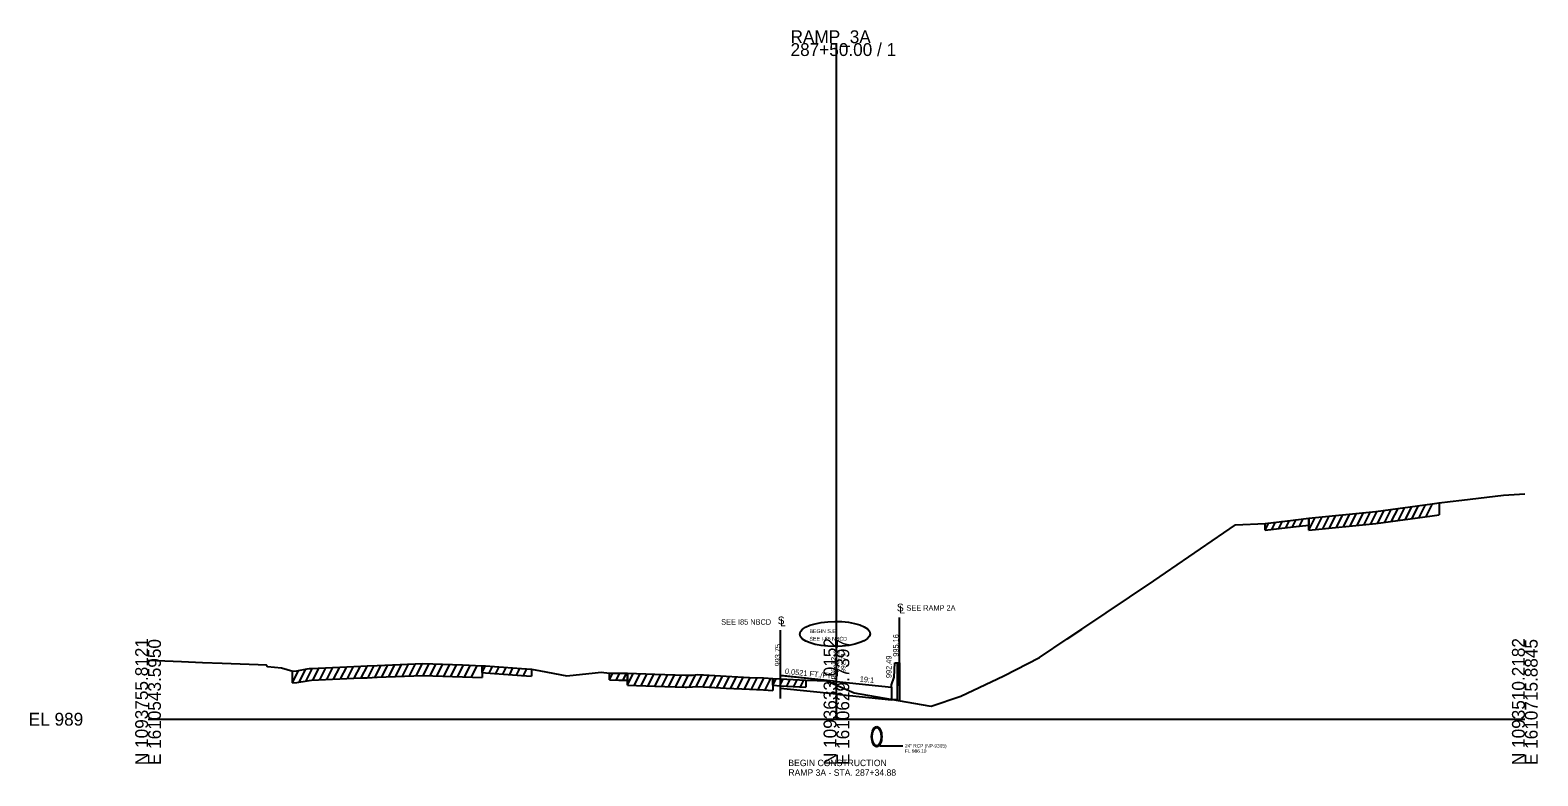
# Model space of a CAD drawing. Extents: x -26 to 1611524, y -12 to 1281970.
# Drawn here: x -25.7 to 302.8, y -12.4 to 150.3 of the extents above; entities that cross this region are included whole.
import ezdxf

# ---------------------------------------------------------------- set-up
doc = ezdxf.new("R2010")
doc.units = 0
for name, color, linetype in [('RD_EX_Misc', 7, 'Continuous'), ('RD_GPK_XS_Cell', 7, 'Continuous'), ('RD_Sketch1', 7, 'Continuous'), ('RD_Sketch6', 7, 'Continuous'), ('RD_XS_Base', 7, 'Continuous'), ('RD_XS_CurbFront', 7, 'Continuous'), ('RD_XS_ExGround', 7, 'Continuous'), ('RD_XS_ExPaveRet', 7, 'Continuous'), ('RD_XS_MatchLine', 7, 'Continuous'), ('RD_XS_MedBbase', 7, 'Continuous'), ('RD_XS_MedBWall', 7, 'Continuous'), ('RD_XS_Pave', 7, 'Continuous'), ('RD_XS_PaveShd', 7, 'Continuous'), ('RD_XS_Pipe', 7, 'Continuous'), ('RD_XS_TX_Elev_EX', 7, 'Continuous'), ('RD_XS_TX_Elev_PR', 7, 'Continuous'), ('RD_XS_TX_MatchLine', 7, 'Continuous'), ('RD_XS_TX_Notes', 7, 'Continuous'), ('RD_XS_TX_ShdSlope', 7, 'Continuous'), ('RD_XS_TX_Slope', 7, 'Continuous')]:
    doc.layers.add(name, color=color, linetype=linetype)

msp = doc.modelspace()

# ---------------------------------------------------------------- linework, layer by layer
at = {"layer": 'RD_EX_Misc'}
for p, q in [((252.97, 43.85), (252.97, 42.35)), ((243.4, 41.2), (243.4, 42.7)), ((243.4, 41.2), (249.5, 41.93)), ((249.5, 41.93), (252.96, 42.35)), ((252.96, 42.35), (252.97, 42.35)), ((72.8, 10.17), (72.8, 11.67)), ((72.8, 10.17), (73.52, 10.12)), ((73.52, 10.12), (81.35, 9.57)), ((83.54, 10.89), (83.54, 9.39)), ((100.53, 8.57), (100.53, 10.07)), ((104.46, 10.03), (104.46, 8.53)), ((81.35, 9.57), (83.54, 9.39)), ((100.53, 8.57), (102.6, 8.54)), ((102.6, 8.54), (104.46, 8.53)), ((136.17, 7.39), (136.17, 8.89)), ((136.17, 7.39), (137.8, 7.29)), ((137.8, 7.29), (143.32, 7.01)), ((143.32, 8.51), (143.32, 7.01))]:
    msp.add_line(p, q, dxfattribs=at)
at = {"layer": 'RD_GPK_XS_Cell'}
for p, q in [((150, 0), (150, 147.42)), ((0, 0), (150, 0)), ((150, 0), (300, 0))]:
    msp.add_line(p, q, dxfattribs=at)
at = {"layer": 'RD_Sketch1'}
for p, q in [((243.4, 41.2), (244.2, 42.8)), ((244.9, 41.38), (245.7, 42.98)), ((246.4, 41.56), (247.2, 43.16)), ((247.91, 41.74), (248.7, 43.34)), ((249.41, 41.92), (250.2, 43.52)), ((250.91, 42.1), (251.7, 43.7)), ((72.8, 10.17), (73.53, 11.62)), ((74.3, 10.07), (75.02, 11.52)), ((75.8, 9.96), (76.52, 11.41)), ((77.3, 9.86), (78.02, 11.3)), ((78.8, 9.75), (79.52, 11.2)), ((80.3, 9.64), (81.02, 11.09)), ((81.8, 9.53), (82.52, 10.97)), ((100.53, 8.57), (101.27, 10.06)), ((102.03, 8.55), (102.77, 10.04)), ((103.53, 8.54), (104.28, 10.03)), ((136.17, 7.39), (136.9, 8.84)), ((137.68, 7.3), (138.41, 8.76)), ((139.18, 7.22), (139.91, 8.69)), ((140.68, 7.15), (141.41, 8.61)), ((142.18, 7.07), (142.91, 8.53))]:
    msp.add_line(p, q, dxfattribs=at)
at = {"layer": 'RD_Sketch6'}
msp.add_line((150, 8.23), (138, 9.48), dxfattribs=at)
at = {"layer": 'RD_XS_Base'}
for p, q in [((137.79, 6.72), (137.79, 8.79)), ((150, 5.45), (137.79, 6.72)), ((150, 5.45), (162, 4.2))]:
    msp.add_line(p, q, dxfattribs=at)
at = {"layer": 'RD_XS_CurbFront'}
for p, q in [((163.25, 12.31), (163.25, 11.65)), ((162, 6.98), (162, 4.2))]:
    msp.add_line(p, q, dxfattribs=at)
at = {"layer": 'RD_XS_ExGround'}
msp.add_lwpolyline([(0, 12.87), (7.28, 12.59), (11.83, 12.4), (16.15, 12.23), (23.97, 11.94), (25.76, 11.84), (25.99, 11.51), (29.09, 11.21), (31.52, 10.5), (32.43, 10.58), (34.64, 11), (35.13, 11.05), (35.59, 11.09), (46.39, 11.6), (47.74, 11.66), (49.94, 11.75), (59.88, 12.15), (68.49, 11.83), (72.8, 11.67), (73.52, 11.62), (81.35, 11.07), (83.54, 10.89), (85.55, 10.55), (91.26, 9.48), (97.46, 10.13), (98.71, 10.23), (100.53, 10.07), (102.6, 10.04), (104.46, 10.03), (110.42, 9.82), (117.03, 9.61), (117.37, 9.61), (118.65, 9.63), (119.81, 9.73), (126, 9.4), (131.09, 9.13), (134.08, 9), (136.17, 8.89), (137.8, 8.79), (143.32, 8.51), (145.79, 8.44), (147.77, 8.43), (150, 7.43), (153.86, 5.74), (170.15, 2.93), (170.63, 2.84), (177.13, 5.05), (186.51, 9.46), (194.23, 13.47), (200.29, 17.56), (203.5, 19.61), (219.16, 30.18), (236.93, 42.4), (243.4, 42.7), (249.5, 43.43), (252.96, 43.85), (267.54, 45.31), (279.79, 46.97), (281.32, 47.19), (283.71, 47.46), (286.29, 47.77), (295.34, 48.86), (300, 49.13)], dxfattribs=at)
at = {"layer": 'RD_XS_ExPaveRet'}
for p, q in [((272.47, 43.38), (273.87, 46.17)), ((273.97, 43.58), (275.37, 46.37)), ((275.47, 43.79), (276.87, 46.58)), ((276.97, 43.99), (278.37, 46.78)), ((278.47, 44.2), (279.87, 46.99)), ((281.32, 47.19), (281.32, 44.59)), ((252.97, 41.25), (254.33, 43.99)), ((252.97, 41.25), (252.97, 43.85)), ((254.47, 41.4), (255.83, 44.14)), ((255.97, 41.55), (257.34, 44.29)), ((257.47, 41.7), (258.84, 44.44)), ((258.97, 41.85), (260.34, 44.59)), ((260.47, 42), (261.84, 44.74)), ((261.97, 42.15), (263.34, 44.89)), ((263.47, 42.3), (264.84, 45.04)), ((264.97, 42.45), (266.34, 45.19)), ((266.47, 42.6), (267.84, 45.35)), ((267.54, 42.71), (279.79, 44.37)), ((267.97, 42.77), (269.37, 45.56)), ((269.47, 42.97), (270.87, 45.76)), ((270.97, 43.18), (272.37, 45.97)), ((279.79, 44.37), (281.32, 44.59)), ((281.32, 44.59), (281.32, 44.59)), ((252.97, 41.25), (267.54, 42.71)), ((31.44, 7.92), (32.81, 10.65)), ((31.44, 7.92), (31.44, 10.52)), ((32.94, 8.08), (34.38, 10.95)), ((34.44, 8.36), (35.81, 11.1)), ((35.94, 8.51), (37.27, 11.17)), ((37.44, 8.58), (38.77, 11.24)), ((38.94, 8.65), (40.27, 11.31)), ((40.44, 8.72), (41.78, 11.38)), ((41.94, 8.79), (43.28, 11.45)), ((43.44, 8.86), (44.78, 11.52)), ((44.94, 8.93), (46.28, 11.59)), ((46.45, 9), (47.78, 11.67)), ((47.95, 9.07), (49.27, 11.73)), ((49.45, 9.13), (50.77, 11.79)), ((50.95, 9.19), (52.27, 11.85)), ((52.45, 9.25), (53.77, 11.91)), ((53.95, 9.31), (55.27, 11.97)), ((55.45, 9.37), (56.78, 12.03)), ((56.95, 9.43), (58.28, 12.09)), ((58.45, 9.49), (59.78, 12.15)), ((59.95, 9.55), (61.23, 12.1)), ((61.45, 9.49), (62.73, 12.04)), ((62.95, 9.44), (64.23, 11.99)), ((64.45, 9.38), (65.73, 11.93)), ((65.95, 9.32), (67.23, 11.87)), ((67.45, 9.27), (68.73, 11.82)), ((68.95, 9.21), (70.23, 11.76)), ((70.45, 9.15), (71.73, 11.71)), ((72.8, 11.67), (72.8, 9.07)), ((104.46, 7.43), (104.46, 10.03)), ((104.46, 7.43), (105.73, 9.99)), ((105.96, 7.38), (107.24, 9.93)), ((107.46, 7.33), (108.74, 9.88)), ((31.44, 7.92), (31.52, 7.9)), ((31.52, 7.9), (32.43, 7.98)), ((32.43, 7.98), (34.64, 8.4)), ((34.64, 8.4), (35.13, 8.45)), ((35.13, 8.45), (35.59, 8.49)), ((35.59, 8.49), (46.39, 9)), ((46.39, 9), (47.74, 9.06)), ((47.74, 9.06), (49.94, 9.15)), ((49.94, 9.15), (59.88, 9.55)), ((59.88, 9.55), (68.49, 9.23)), ((68.49, 9.23), (72.8, 9.07)), ((104.46, 7.43), (110.42, 7.22)), ((108.96, 7.27), (110.24, 9.83)), ((110.42, 7.22), (117.03, 7.01)), ((110.46, 7.22), (111.74, 9.78)), ((111.96, 7.17), (113.24, 9.73)), ((113.46, 7.12), (114.74, 9.68)), ((114.96, 7.08), (116.24, 9.64)), ((116.46, 7.03), (117.76, 9.62)), ((117.03, 7.01), (117.37, 7.01)), ((117.37, 7.01), (118.65, 7.03)), ((117.96, 7.02), (119.29, 9.69)), ((118.65, 7.03), (119.81, 7.13)), ((119.46, 7.1), (120.75, 9.68)), ((119.81, 7.13), (126, 6.8)), ((120.96, 7.07), (122.23, 9.6)), ((122.46, 6.99), (123.73, 9.52)), ((123.96, 6.91), (125.23, 9.44)), ((125.46, 6.83), (126.73, 9.36)), ((126, 6.8), (131.09, 6.53)), ((126.96, 6.75), (128.23, 9.28)), ((128.46, 6.67), (129.73, 9.21)), ((129.97, 6.59), (131.23, 9.13)), ((131.47, 6.52), (132.74, 9.06)), ((132.97, 6.45), (134.24, 8.99)), ((134.47, 6.38), (135.73, 8.91)), ((136.17, 8.89), (136.17, 6.29)), ((131.09, 6.53), (134.08, 6.4)), ((134.08, 6.4), (136.17, 6.29)), ((136.17, 6.29), (136.17, 6.29))]:
    msp.add_line(p, q, dxfattribs=at)
at = {"layer": 'RD_XS_MatchLine'}
for p, q in [((163.75, 12.31), (163.75, 4.03)), ((137.79, 8.79), (137.79, 9.5))]:
    msp.add_line(p, q, dxfattribs=at)
at = {"layer": 'RD_XS_MedBbase'}
for p, q in [((163.75, 11.65), (163.25, 11.65)), ((163.25, 11.65), (163.25, 4.2)), ((163.75, 12.31), (163.75, 11.65)), ((163.25, 4.2), (162, 4.2))]:
    msp.add_line(p, q, dxfattribs=at)
at = {"layer": 'RD_XS_MedBWall'}
for p, q in [((162.58, 9.15), (162.75, 12.31)), ((162.75, 12.31), (163.25, 12.31)), ((163.25, 12.31), (163.75, 12.31)), ((162, 7.48), (162.58, 9.15)), ((162, 6.98), (162, 7.48))]:
    msp.add_line(p, q, dxfattribs=at)
at = {"layer": 'RD_XS_Pave'}
msp.add_line((150, 8.23), (137.79, 9.5), dxfattribs=at)
at = {"layer": 'RD_XS_PaveShd'}
msp.add_line((150, 8.23), (162, 6.98), dxfattribs=at)
at = {"layer": 'RD_XS_Pipe'}
msp.add_line((159.44, -5.81), (164.44, -5.81), dxfattribs=at)
for major_axis in [(0, 2.2), (0, 2)]:
    msp.add_ellipse((158.77, -3.81), major_axis=major_axis, ratio=0.5, dxfattribs=at)
at = {"layer": 'RD_XS_TX_MatchLine'}
for p, q in [((163.75, 12.31), (163.75, 22.2)), ((137.79, 9.5), (137.79, 19.39)), ((163.75, 7.31), (163.75, 12.31)), ((137.79, 4.5), (137.79, 9.5))]:
    msp.add_line(p, q, dxfattribs=at)
at = {"layer": 'RD_XS_TX_Notes'}
msp.add_ellipse((149.67, 18.6), major_axis=(7.68, 0.05), ratio=0.355189, dxfattribs=at)

# ---------------------------------------------------------------- texts
at = {"layer": 'RD_GPK_XS_Cell'}
for s, p in [('RAMP_3A', (140, 147.42)), ('287+50.00 / 1', (140, 144.62)), ('EL 989', (-26, -1.4))]:
    msp.add_text(s, height=2.8, dxfattribs=at).set_placement(p)
for s, p in [('N 1093755.8121', (0, -10)), ('E 1610543.5950', (2.8, -10)), ('N 1093633.0152', (150, -10)), ('E 1610629.7397', (152.8, -10)), ('N 1093510.2182', (300, -10)), ('E 1610715.8845', (302.8, -10))]:
    msp.add_text(s, height=2.8, rotation=90, dxfattribs=at).set_placement(p)
at = {"layer": 'RD_Sketch6'}
msp.add_text(' 993.12', height=1.2, rotation=90, dxfattribs=at).set_placement((150, 8.23))
at = {"layer": 'RD_XS_Pipe'}
for s, p in [('24" RCP (NP-9305)', (164.94, -6.18)), ('FL 986.10', (164.94, -7.31))]:
    msp.add_text(s, height=0.75, dxfattribs=at).set_placement(p)
at = {"layer": 'RD_XS_TX_Elev_EX'}
msp.add_text('992.71', height=1, rotation=90, dxfattribs=at).set_placement((151.97, 10.2))
at = {"layer": 'RD_XS_TX_Elev_PR'}
for s, p in [('995.16', (163.53, 13.64)), ('993.75', (137.79, 11.5)), ('993.12', (150.6, 10.23)), ('992.49', (162, 8.98))]:
    msp.add_text(s, height=1.2, rotation=90, dxfattribs=at).set_placement(p)
at = {"layer": 'RD_XS_TX_MatchLine'}
for s, p in [('S', (163.17, 23.52)), ('L', (163.68, 23.08)), ('S', (137.2, 20.71)), ('L', (137.72, 20.27))]:
    msp.add_text(s, height=1.68, dxfattribs=at).set_placement(p)
at = {"layer": 'RD_XS_TX_Notes'}
for s, p in [('SEE RAMP 2A', (165.25, 23.66)), ('SEE I85 NBCD', (124.89, 20.61))]:
    msp.add_text(s, height=1.2, rotation=360, dxfattribs=at).set_placement(p)
for s, height, p in [('SEE I-85 NBCD', 0.8333, (144.12, 17.13)), ('BEGIN S.E.', 0.833, (144.12, 18.79)), ('BEGIN CONSTRUCTION', 1.4, (139.53, -10.23)), ('RAMP 3A - STA. 287+34.88', 1.4, (139.53, -12.33))]:
    msp.add_text(s, height=height, dxfattribs=at).set_placement(p)
at = {"layer": 'RD_XS_TX_ShdSlope'}
msp.add_text('19:1', height=1.2, rotation=354.0555, dxfattribs=at).set_placement((155.04, 8.21))
at = {"layer": 'RD_XS_TX_Slope'}
msp.add_text('0.0521 FT./FT.', height=1.2, rotation=354.0555, dxfattribs=at).set_placement((138.73, 9.9))

doc.saveas('drawing.dxf')
